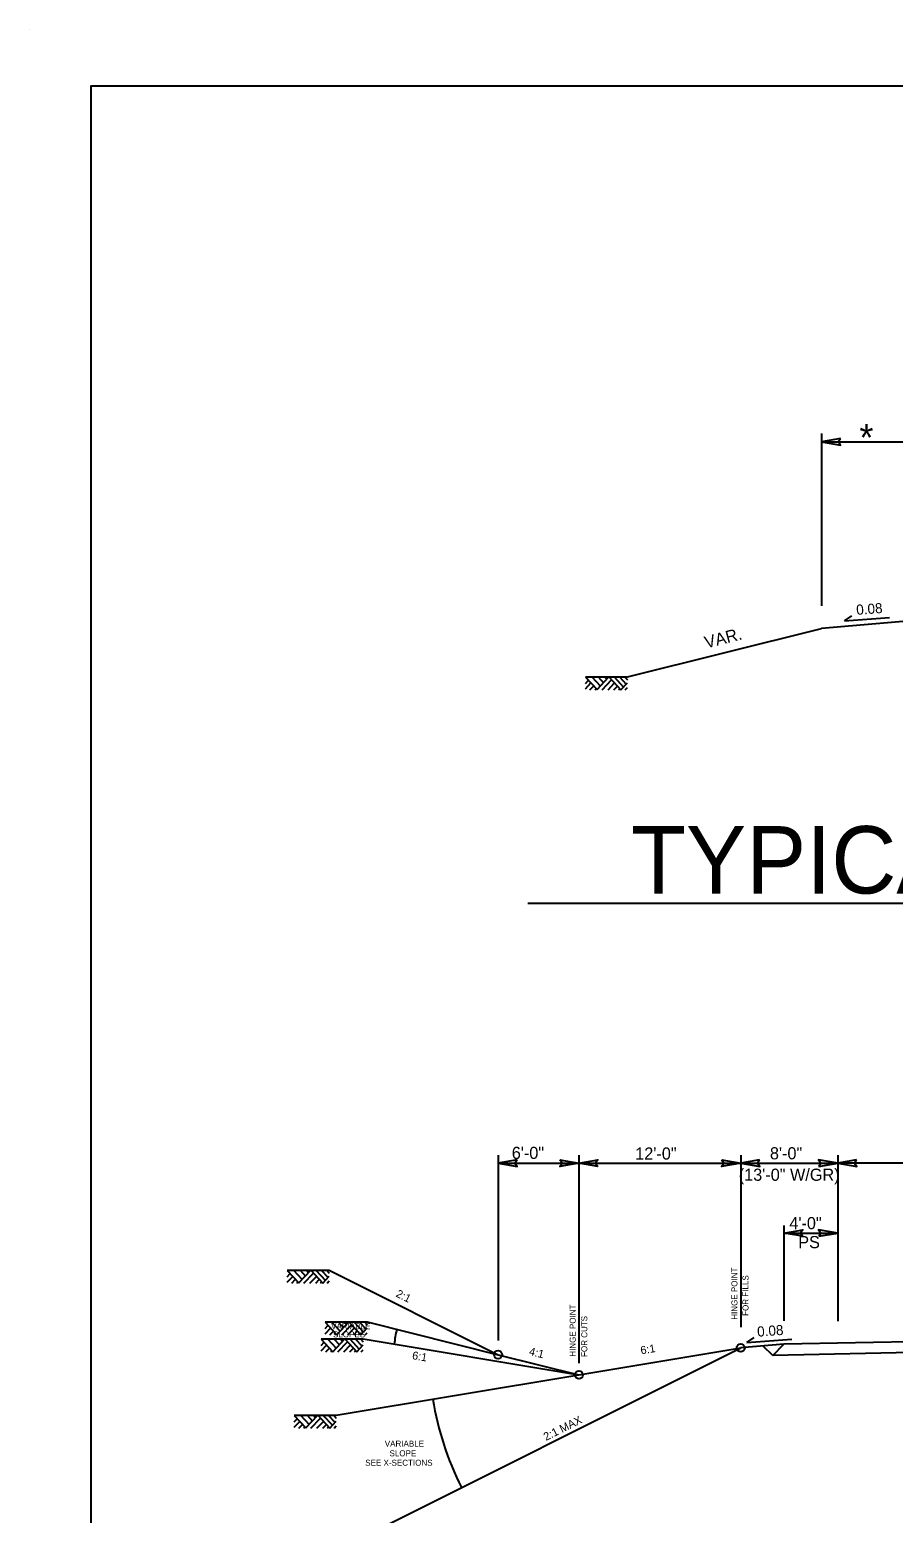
# Model space of a CAD drawing. Extents: x 1904401 to 1905163, y 193929 to 194736.
# Drawn here: x 1904498 to 1904562, y 194245.4 to 194355.4 of the extents above; entities that cross this region are included whole.
import ezdxf

# ---------------------------------------------------------------- set-up
doc = ezdxf.new("R2010")
doc.units = 0
for name, color, linetype in [('Old_Level_2', 7, 'Continuous'), ('Prop Lane Arrow CELL', 7, 'Continuous'), ('Scratch_Level_3', 7, 'Continuous'), ('Typical Arrow Superelevation CELL', 7, 'Continuous'), ('Typical Hinge Slope Arterial CELL', 7, 'Continuous'), ('Typical Hinge Slope Interstate CELL', 7, 'Continuous'), ('Typical Terminator CELL', 7, 'Continuous')]:
    doc.layers.add(name, color=color, linetype=linetype)

msp = doc.modelspace()

# ---------------------------------------------------------------- linework, layer by layer
at = {"layer": 'Old_Level_2'}
msp.add_lwpolyline([(1904502.51, 194232.16), (1904658.33, 194232.16), (1904658.33, 194351.23), (1904502.51, 194351.23)], close=True, dxfattribs=at)
at = {"layer": 'Prop Lane Arrow CELL'}
for p, q in [((1904556.72, 194325.46), (1904556.72, 194312.68)), ((1904556.72, 194324.86), (1904563.92, 194324.86)), ((1904563.92, 194311.61), (1904556.72, 194311.01)), ((1904539.2, 194307.4), (1904540.07, 194306.47)), ((1904539.2, 194306.92), (1904539.42, 194307.16)), ((1904539.2, 194306.52), (1904539.61, 194306.96)), ((1904539.54, 194306.44), (1904539.82, 194306.74)), ((1904539.67, 194307.41), (1904540.31, 194306.72)), ((1904540.07, 194306.47), (1904540.94, 194307.41)), ((1904540.14, 194307.41), (1904540.54, 194306.98)), ((1904540.44, 194306.44), (1904541.14, 194307.2)), ((1904540.63, 194307.41), (1904540.79, 194307.24)), ((1904540.88, 194306.44), (1904541.36, 194306.96)), ((1904540.94, 194307.41), (1904541.83, 194306.45)), ((1904541.32, 194306.44), (1904541.58, 194306.72)), ((1904541.33, 194307.41), (1904542.03, 194306.66)), ((1904541.73, 194307.41), (1904542.23, 194306.88)), ((1904541.83, 194306.45), (1904542.32, 194306.98)), ((1904542.11, 194307.41), (1904542.32, 194307.19)), ((1904539.92, 194306.44), (1904540, 194306.53)), ((1904541.68, 194306.44), (1904541.76, 194306.53)), ((1904542.16, 194306.44), (1904542.32, 194306.62)), ((1904534.93, 194290.62), (1904616.21, 194290.62)), ((1904532.72, 194271.94), (1904532.72, 194258.17)), ((1904538.72, 194271.94), (1904538.72, 194256.51)), ((1904550.72, 194271.94), (1904550.72, 194259.17)), ((1904557.92, 194271.94), (1904557.92, 194259.61)), ((1904532.72, 194271.34), (1904557.92, 194271.34)), ((1904569.92, 194271.34), (1904557.92, 194271.34)), ((1904553.92, 194266.72), (1904553.92, 194259.63)), ((1904553.92, 194266.15), (1904557.92, 194266.15)), ((1904517.08, 194263.38), (1904517.95, 194262.45)), ((1904517.08, 194262.9), (1904517.3, 194263.14)), ((1904517.08, 194262.5), (1904517.49, 194262.94)), ((1904517.43, 194262.43), (1904517.7, 194262.72)), ((1904517.55, 194263.39), (1904518.19, 194262.7)), ((1904517.95, 194262.45), (1904518.83, 194263.39)), ((1904518.03, 194263.39), (1904518.43, 194262.96)), ((1904518.32, 194262.43), (1904519.02, 194263.18)), ((1904518.51, 194263.39), (1904518.67, 194263.22)), ((1904518.77, 194262.43), (1904519.25, 194262.94)), ((1904518.83, 194263.39), (1904519.72, 194262.44)), ((1904519.2, 194262.43), (1904519.46, 194262.71)), ((1904519.21, 194263.39), (1904519.91, 194262.64)), ((1904519.61, 194263.39), (1904520.11, 194262.86)), ((1904519.72, 194262.44), (1904520.2, 194262.96)), ((1904520, 194263.39), (1904520.2, 194263.17)), ((1904517.8, 194262.43), (1904517.88, 194262.52)), ((1904519.56, 194262.43), (1904519.64, 194262.51)), ((1904520.04, 194262.43), (1904520.2, 194262.6)), ((1904519.9, 194259.55), (1904520.77, 194258.61)), ((1904520.37, 194259.56), (1904521.01, 194258.87)), ((1904520.77, 194258.61), (1904521.65, 194259.56)), ((1904520.85, 194259.56), (1904521.25, 194259.13)), ((1904521.33, 194259.56), (1904521.49, 194259.39)), ((1904521.65, 194259.56), (1904522.54, 194258.6)), ((1904522.03, 194259.56), (1904522.73, 194258.81)), ((1904522.43, 194259.56), (1904522.93, 194259.02)), ((1904522.82, 194259.56), (1904523.02, 194259.34)), ((1904519.6, 194258.29), (1904520.47, 194257.35)), ((1904519.9, 194259.07), (1904520.12, 194259.31)), ((1904519.9, 194258.67), (1904520.31, 194259.11)), ((1904520.07, 194258.3), (1904520.71, 194257.61)), ((1904520.25, 194258.59), (1904520.52, 194258.88)), ((1904520.47, 194257.35), (1904521.35, 194258.3)), ((1904520.55, 194258.3), (1904520.95, 194257.87)), ((1904520.62, 194258.59), (1904520.7, 194258.68)), ((1904521.03, 194258.3), (1904521.19, 194258.13)), ((1904521.14, 194258.59), (1904521.84, 194259.34)), ((1904521.35, 194258.3), (1904522.24, 194257.34)), ((1904521.59, 194258.59), (1904522.07, 194259.11)), ((1904521.73, 194258.3), (1904522.43, 194257.55)), ((1904522.02, 194258.59), (1904522.28, 194258.87)), ((1904522.13, 194258.3), (1904522.63, 194257.77)), ((1904522.38, 194258.59), (1904522.46, 194258.68)), ((1904522.52, 194258.3), (1904522.72, 194258.08)), ((1904522.54, 194258.6), (1904523.02, 194259.12)), ((1904522.86, 194258.59), (1904523.02, 194258.76)), ((1904575.92, 194258.34), (1904553.92, 194257.9)), ((1904519.6, 194257.81), (1904519.82, 194258.05)), ((1904519.6, 194257.41), (1904520.01, 194257.85)), ((1904519.95, 194257.33), (1904520.22, 194257.62)), ((1904520.32, 194257.33), (1904520.41, 194257.42)), ((1904520.84, 194257.33), (1904521.55, 194258.09)), ((1904521.29, 194257.33), (1904521.77, 194257.85)), ((1904521.73, 194257.33), (1904521.99, 194257.61)), ((1904522.08, 194257.33), (1904522.16, 194257.42)), ((1904522.24, 194257.34), (1904522.72, 194257.86)), ((1904522.56, 194257.33), (1904522.72, 194257.5)), ((1904553.92, 194257.9), (1904550.72, 194257.63)), ((1904553.1, 194257.08), (1904552.4, 194257.77)), ((1904553.1, 194257.08), (1904553.92, 194257.9)), ((1904575.93, 194257.53), (1904553.1, 194257.08)), ((1904517.6, 194252.62), (1904518.47, 194251.69)), ((1904517.6, 194252.14), (1904517.83, 194252.38)), ((1904517.6, 194251.74), (1904518.01, 194252.18)), ((1904517.95, 194251.67), (1904518.22, 194251.96)), ((1904518.07, 194252.63), (1904518.71, 194251.95)), ((1904518.32, 194251.67), (1904518.41, 194251.76)), ((1904518.47, 194251.69), (1904519.35, 194252.63)), ((1904518.55, 194252.63), (1904518.95, 194252.2)), ((1904518.84, 194251.67), (1904519.55, 194252.42)), ((1904519.03, 194252.63), (1904519.19, 194252.46)), ((1904519.29, 194251.67), (1904519.77, 194252.18)), ((1904519.35, 194252.63), (1904520.24, 194251.68)), ((1904519.73, 194252.63), (1904520.43, 194251.89)), ((1904519.73, 194251.67), (1904519.99, 194251.95)), ((1904520.08, 194251.67), (1904520.16, 194251.76)), ((1904520.13, 194252.63), (1904520.63, 194252.1)), ((1904520.24, 194251.68), (1904520.72, 194252.2)), ((1904520.52, 194252.63), (1904520.72, 194252.41)), ((1904520.56, 194251.67), (1904520.72, 194251.84))]:
    msp.add_line(p, q, dxfattribs=at)
for points in [[(1904539.2, 194307.41), (1904542.32, 194307.41)], [(1904517.08, 194263.39), (1904520.2, 194263.39)], [(1904519.9, 194259.56), (1904523.02, 194259.56)], [(1904519.6, 194258.3), (1904522.72, 194258.3)], [(1904517.6, 194252.63), (1904520.72, 194252.63)]]:
    msp.add_lwpolyline(points, dxfattribs=at)
at = {"layer": 'Scratch_Level_3'}
msp.add_line((1904497.98, 194355.42), (1904497.98, 194355.42), dxfattribs=at)
at = {"layer": 'Typical Arrow Superelevation CELL'}
for p, q in [((1904558.42, 194311.57), (1904558.96, 194311.94)), ((1904558.42, 194311.57), (1904561.77, 194311.81)), ((1904551.17, 194258.03), (1904551.72, 194258.4)), ((1904551.17, 194258.03), (1904554.52, 194258.28))]:
    msp.add_line(p, q, dxfattribs=at)
at = {"layer": 'Typical Hinge Slope Arterial CELL'}
for p, q in [((1904520.2, 194263.39), (1904532.72, 194257.13)), ((1904523.02, 194259.56), (1904532.72, 194257.13)), ((1904522.72, 194258.3), (1904538.72, 194255.63)), ((1904520.72, 194242.63), (1904550.72, 194257.63)), ((1904538.72, 194255.63), (1904550.72, 194257.63)), ((1904532.72, 194257.13), (1904538.72, 194255.63)), ((1904520.72, 194252.63), (1904538.72, 194255.63))]:
    msp.add_line(p, q, dxfattribs=at)
for centre in [(1904532.72, 194257.13), (1904550.72, 194257.63), (1904538.72, 194255.63)]:
    msp.add_circle(centre, 0.297, dxfattribs=at)
for centre, radius, start, end in [((1904532.72, 194257.13), 7.74, 165.9637, 174.1897), ((1904550.72, 194257.63), 23.16, 189.4624, 206.565)]:
    msp.add_arc(centre, radius, start, end, dxfattribs=at)
at = {"layer": 'Typical Hinge Slope Interstate CELL'}
msp.add_line((1904542.32, 194307.41), (1904556.72, 194311.01), dxfattribs=at)
at = {"layer": 'Typical Terminator CELL'}
for points in [[(1904558.12, 194325.1), (1904556.72, 194324.86), (1904558.13, 194324.61), (1904557.95, 194324.86)], [(1904534.13, 194271.59), (1904532.72, 194271.34), (1904534.13, 194271.09), (1904533.95, 194271.34)], [(1904537.31, 194271.59), (1904538.72, 194271.34), (1904537.31, 194271.09), (1904537.49, 194271.34)], [(1904540.13, 194271.1), (1904538.72, 194271.34), (1904540.13, 194271.59), (1904539.95, 194271.34)], [(1904549.31, 194271.59), (1904550.72, 194271.34), (1904549.3, 194271.09), (1904549.48, 194271.34)], [(1904552.12, 194271.59), (1904550.72, 194271.34), (1904552.13, 194271.09), (1904551.95, 194271.34)], [(1904556.51, 194271.1), (1904557.92, 194271.34), (1904556.5, 194271.59), (1904556.68, 194271.34)], [(1904559.32, 194271.59), (1904557.92, 194271.34), (1904559.33, 194271.09), (1904559.15, 194271.34)], [(1904555.32, 194265.91), (1904553.92, 194266.15), (1904555.33, 194266.4), (1904555.15, 194266.15)], [(1904556.51, 194265.91), (1904557.92, 194266.15), (1904556.5, 194266.4), (1904556.68, 194266.15)]]:
    msp.add_lwpolyline(points, close=True, dxfattribs=at)

# ---------------------------------------------------------------- texts
at = {"layer": 'Prop Lane Arrow CELL'}
for s, height, p in [('*', 2, (1904559.53, 194324.17)), ('TYPICAL SECTION 2', 5, (1904542.58, 194291.34)), ('6\'-0"', 0.9, (1904533.74, 194271.65)), ('12\'-0"', 0.9, (1904542.9, 194271.6)), ('8\'-0"', 0.9, (1904552.89, 194271.62)), ('(13\'-0" W/GR)', 0.9, (1904550.58, 194270.03)), ('4\'-0"', 0.9, (1904554.33, 194266.44)), ('PS', 0.9, (1904554.99, 194265.03))]:
    msp.add_text(s, height=height, dxfattribs=at).set_placement(p)
for p in [(1904559.32, 194312.01), (1904551.97, 194258.46)]:
    msp.add_text('0.08', height=0.75, rotation=4.1982, dxfattribs=at).set_placement(p)
at = {"layer": 'Typical Hinge Slope Arterial CELL'}
for s, height, rotation, p in [('HINGE POINT ', 0.4452, 90, (1904550.48, 194259.72)), ('FOR FILLS', 0.445, 90, (1904551.3, 194260.01)), ('2:1', 0.594, 333.435, (1904525.09, 194261.46)), ('HINGE POINT ', 0.4452, 90, (1904538.48, 194256.98)), ('FOR CUTS', 0.445, 90, (1904539.34, 194256.96)), ('6:1', 0.594, 350.5365, (1904526.32, 194256.8)), ('4:1', 0.594, 345.9638, (1904534.98, 194257.12)), ('6:1', 0.594, 9.4623, (1904543.34, 194257.15)), ('2:1 MAX', 0.594, 26.5651, (1904536.28, 194250.73))]:
    msp.add_text(s, height=height, rotation=rotation, dxfattribs=at).set_placement(p)
for s, height, p in [('VARIABLE ', 0.445, (1904520.34, 194259.02)), ('SLOPES', 0.445, (1904520.48, 194258.41)), ('VARIABLE ', 0.445, (1904524.32, 194250.31)), ('SLOPE', 0.445, (1904524.67, 194249.59)), ('SEE X-SECTIONS', 0.4452, (1904522.87, 194248.89))]:
    msp.add_text(s, height=height, dxfattribs=at).set_placement(p)
at = {"layer": 'Typical Hinge Slope Interstate CELL'}
msp.add_text('VAR.', height=0.9, rotation=14.4716, dxfattribs=at).set_placement((1904548.17, 194309.51))

doc.saveas('drawing.dxf')
